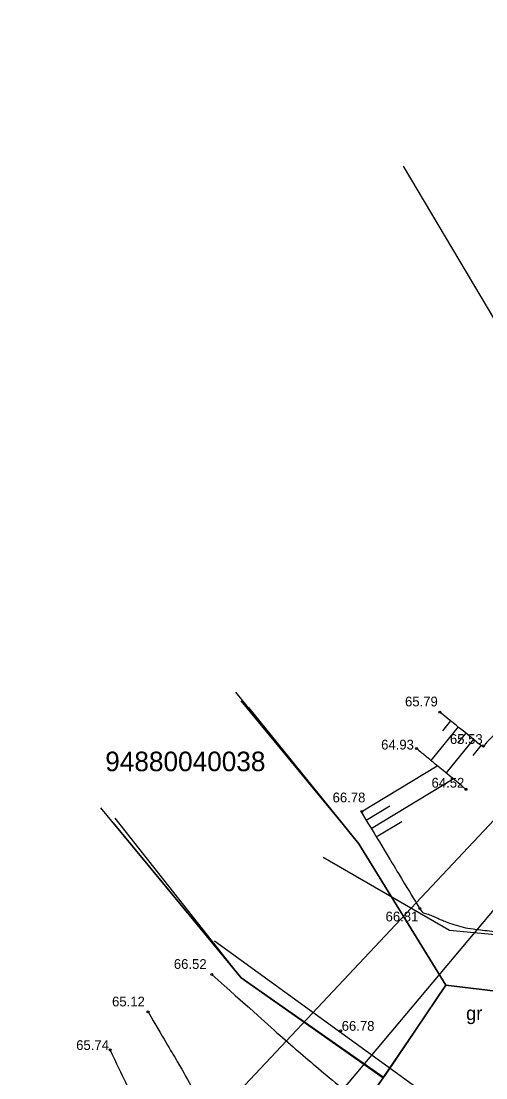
# Model space of a CAD drawing. Extents: x 616607 to 617499, y 408385 to 409695.
# Drawn here: x 617313.7 to 617337.4, y 409529.6 to 409583.6 of the extents above; entities that cross this region are included whole.
import ezdxf

# ---------------------------------------------------------------- set-up
doc = ezdxf.new("R2010")
doc.units = 0
for name, color, linetype in [('BUVE_INZE_VEKT_####_#', 7, 'Continuous'), ('CELI_CMAL_####_####_#', 7, 'Continuous'), ('CELI_CSEG_####_TKST_#', 7, 'Continuous'), ('DREN_VADP_####_####_#', 7, 'Continuous'), ('HIDT_CAUR_####_####_#', 7, 'Continuous'), ('RAMI_UZMR_####_####_#', 7, 'Continuous'), ('RELJ_AATZ_####_TKST_#', 7, 'Continuous'), ('RELJ_ELEM_####_####_#', 7, 'Continuous'), ('RELJ_NOGA_####_####_#', 7, 'Continuous'), ('RELJ_NOGL_####_####_#', 7, 'Continuous'), ('ROBZ_IERR_####_####_#', 7, 'Continuous'), ('ROBZ_PROJ_####_####_#', 7, 'Continuous'), ('ROBZ_PROJ_####_TKST_#', 7, 'Continuous'), ('ROBZ_UZMR_####_####_#', 7, 'Continuous')]:
    doc.layers.add(name, color=color, linetype=linetype)

# ---------------------------------------------------------------- blocks, each defined once
blk = doc.blocks.new('PKT')
at = {"layer": 'RELJ_ELEM_####_####_#'}
blk.add_circle((0, 0), 0.05, dxfattribs=at)

msp = doc.modelspace()

# ---------------------------------------------------------------- linework, layer by layer
at = {"layer": 'BUVE_INZE_VEKT_####_#'}
msp.add_lwpolyline([(617324.923, 409548.853), (617330.95, 409541.554), (617335.391, 409534.333), (617332.184, 409529.625), (617324.935, 409534.695), (617318.501, 409542.857)], dxfattribs=at)
at = {"layer": 'CELI_CMAL_####_####_#'}
for points in [[(617329.129, 409540.872), (617335.578, 409537.138), (617339.527, 409536.758), (617344.023, 409537.049), (617347.209, 409538.054), (617350.956, 409540.638)], [(617323.58, 409536.589), (617338.621, 409525.673)]]:
    msp.add_lwpolyline(points, dxfattribs=at)
at = {"layer": 'DREN_VADP_####_####_#'}
msp.add_lwpolyline([(617345.447, 409555.599), (617333.219, 409576.192)], dxfattribs=at)
at = {"layer": 'HIDT_CAUR_####_####_#'}
msp.add_lwpolyline([(617328.298, 409526.812), (617339.023, 409539.598)], dxfattribs=at)
at = {"layer": 'RAMI_UZMR_####_####_#'}
msp.add_lwpolyline([(617101.571, 408748.246), (617213.472, 409074.039), (617215.883, 409140.56), (617165.121, 409241.478), (617252.137, 409353.424), (617269.572, 409425.099), (617332.631, 409510.312), (617439.945, 409622.037), (617425.373, 409635.959), (617242.079, 409440.82), (617216.614, 409355.716), (617136.613, 409246.751), (617191.828, 409115.62), (617145.545, 408952.8)], dxfattribs=at)
at = {"layer": 'RELJ_NOGA_####_####_#'}
for p, q in [((617335.629, 409547.841), (617335.211, 409547.327)), ((617335.241, 409548.156), (617335.241, 409548.155)), ((617335.629, 409547.841), (617335.629, 409547.84)), ((617336.017, 409547.525), (617334.623, 409545.811)), ((617336.405, 409547.209), (617335.986, 409546.695)), ((617336.017, 409547.525), (617336.016, 409547.524)), ((617336.405, 409547.209), (617336.405, 409547.209)), ((617336.793, 409546.894), (617335.395, 409545.176)), ((617336.793, 409546.894), (617336.792, 409546.893)), ((617337.18, 409546.578), (617336.761, 409546.062)), ((617337.18, 409546.578), (617337.18, 409546.578)), ((617331.056, 409543.191), (617334.945, 409545.545)), ((617331.574, 409542.336), (617335.764, 409544.872)), ((617331.315, 409542.764), (617332.527, 409543.497)), ((617331.056, 409543.191), (617331.057, 409543.192)), ((617331.315, 409542.764), (617331.315, 409542.764)), ((617331.574, 409542.336), (617331.575, 409542.336)), ((617331.833, 409541.908), (617333.135, 409542.696)), ((617331.833, 409541.908), (617331.833, 409541.908)), ((617332.092, 409541.48), (617332.092, 409541.481)), ((617332.35, 409541.053), (617332.351, 409541.053)), ((617332.609, 409540.625), (617332.61, 409540.625)), ((617332.868, 409540.197), (617332.868, 409540.197)), ((617333.127, 409539.769), (617333.128, 409539.77)), ((617333.386, 409539.342), (617333.386, 409539.342)), ((617333.645, 409538.914), (617333.646, 409538.914)), ((617333.904, 409538.486), (617333.904, 409538.486)), ((617334.2, 409538.089), (617334.201, 409538.09)), ((617334.656, 409537.887), (617334.656, 409537.888)), ((617335.113, 409537.684), (617335.113, 409537.685)), ((617335.58, 409537.506), (617335.58, 409537.506)), ((617335.58, 409537.506), (617335.58, 409537.506)), ((617336.057, 409537.357), (617336.057, 409537.358)), ((617336.057, 409537.356), (617336.057, 409537.357)), ((617336.543, 409537.24), (617336.543, 409537.24)), ((617336.544, 409537.242), (617336.544, 409537.242)), ((617337.038, 409537.168), (617337.038, 409537.169)), ((617337.038, 409537.167), (617337.038, 409537.168)), ((617318.26, 409530.987), (617318.259, 409530.987)), ((617318.26, 409530.987), (617318.261, 409530.988)), ((617318.477, 409530.537), (617318.476, 409530.537)), ((617318.477, 409530.537), (617318.477, 409530.537)), ((617318.694, 409530.086), (617318.693, 409530.086)), ((617318.694, 409530.086), (617318.694, 409530.087)), ((617318.911, 409529.636), (617318.91, 409529.636)), ((617318.911, 409529.636), (617318.911, 409529.636))]:
    msp.add_line(p, q, dxfattribs=at)
for points in [[(617405.903, 409615.582), (617390.969, 409600.632), (617376.035, 409585.682), (617361.1, 409570.732), (617353.162, 409562.786), (617345.334, 409554.728), (617337.455, 409546.726), (617337.388, 409546.658), (617337.328, 409546.458), (617337.253, 409546.519), (617336.529, 409547.109), (617335.804, 409547.698), (617335.079, 409548.288)], [(617331.056, 409543.191), (617332.054, 409541.542), (617333.052, 409539.893), (617334.051, 409538.243), (617334.188, 409538.016), (617334.501, 409537.961), (617334.744, 409537.85), (617334.977, 409537.743), (617335.205, 409537.638), (617335.447, 409537.552), (617335.916, 409537.385), (617336.387, 409537.247), (617336.878, 409537.187), (617337.849, 409537.069), (617338.82, 409537.003), (617339.794, 409537), (617340.122, 409536.999), (617340.45, 409536.997), (617340.777, 409537.001)], [(617323.43, 409534.875), (617325.254, 409533.269), (617327.041, 409531.618), (617328.903, 409530.056), (617331.485, 409527.887), (617334.171, 409525.842), (617336.806, 409523.735)], [(617148.095, 409250.281), (617149.367, 409254.282), (617150.639, 409258.284), (617151.912, 409262.285), (617156.597, 409277.022), (617171.021, 409286.603), (617180.379, 409298.915), (617194.802, 409317.89), (617212.921, 409334.355), (617223.034, 409356.295), (617225.913, 409362.541), (617226.817, 409369.327), (617228.782, 409375.821), (617233.86, 409392.605), (617237.843, 409409.628), (617244.376, 409426.063), (617252.258, 409445.895), (617268.673, 409460.708), (617281.86, 409477.296), (617294.583, 409493.301), (617307.725, 409508.821), (617320.496, 409524.825), (617320.543, 409524.885), (617320.584, 409524.948), (617320.623, 409525.013), (617320.843, 409525.374), (617320.906, 409525.909), (617320.728, 409526.275), (617320.636, 409526.463), (617320.388, 409526.567), (617320.294, 409526.764), (617319.61, 409528.184), (617318.926, 409529.604), (617318.242, 409531.024)]]:
    msp.add_open_spline(points, degree=3, dxfattribs=at)
at = {"layer": 'RELJ_NOGL_####_####_#'}
for points in [[(617336.415, 409544.336), (617335.809, 409544.835), (617335.203, 409545.333), (617334.597, 409545.832), (617334.359, 409546.028), (617334.122, 409546.224), (617333.884, 409546.421)], [(617320.178, 409532.963), (617320.946, 409531.637), (617321.747, 409530.328), (617322.481, 409528.983), (617323.001, 409528.03), (617323.474, 409527.05), (617323.97, 409526.084)]]:
    msp.add_open_spline(points, degree=3, dxfattribs=at)
at = {"layer": 'ROBZ_IERR_####_####_#'}
msp.add_lwpolyline([(617350.237, 409580.038), (617370.73, 409556.7), (617349.913, 409536.856), (617341.051, 409533.641), (617335.391, 409534.333), (617330.95, 409541.554), (617324.668, 409549.301)], dxfattribs=at)
at = {"layer": 'ROBZ_PROJ_####_####_#'}
for points in [[(617325.305, 409548.516), (617330.95, 409541.554), (617335.391, 409534.333), (617332.358, 409529.835), (617332.188, 409529.592), (617324.935, 409534.695), (617317.766, 409543.393)], [(617318.399, 409542.625), (617324.935, 409534.695), (617332.188, 409529.592), (617326.39, 409521.291), (617255.789, 409432.426), (617250.98, 409414.497), (617224.174, 409428.057)]]:
    msp.add_lwpolyline(points, dxfattribs=at)
at = {"layer": 'ROBZ_UZMR_####_####_#'}
msp.add_lwpolyline([(617232.583, 409073.745), (617196.025, 409075.262), (617200.886, 409119.423), (617196.507, 409136.07), (617150.138, 409230.13), (617148.652, 409247.272), (617201.229, 409318.934), (617233.453, 409357.938), (617244.928, 409391.934), (617250.98, 409414.497), (617255.789, 409432.426), (617326.39, 409521.291), (617332.188, 409529.592), (617332.358, 409529.835), (617335.391, 409534.333), (617341.051, 409533.641), (617349.913, 409536.856), (617370.73, 409556.7), (617378.749, 409547.935), (617381.343, 409545.1)], dxfattribs=at)

# ---------------------------------------------------------------- block references
at = {"layer": 'RELJ_ELEM_####_####_#'}
for p in [(617335.079, 409548.288), (617333.884, 409546.421), (617337.289, 409546.555), (617336.415, 409544.336), (617331.103, 409543.209), (617334.051, 409538.243), (617323.43, 409534.875), (617320.178, 409532.963), (617330.015, 409531.99), (617318.242, 409531.024)]:
    msp.add_blockref('PKT', p, dxfattribs=at)

# ---------------------------------------------------------------- texts
at = {"layer": 'CELI_CSEG_####_TKST_#'}
msp.add_text('gr', height=0.7, dxfattribs=at).set_placement((617336.418, 409532.541))
at = {"layer": 'RELJ_AATZ_####_TKST_#'}
for s, p in [('65.79', (617333.302, 409548.576)), ('64.93', (617332.082, 409546.371)), ('65.53', (617335.594, 409546.658)), ('64.52', (617334.655, 409544.423)), ('66.78', (617329.605, 409543.67)), ('66.81', (617332.308, 409537.586)), ('66.52', (617321.498, 409535.158)), ('65.12', (617318.342, 409533.24)), ('66.78', (617330.068, 409531.995)), ('65.74', (617316.51, 409531.012))]:
    msp.add_text(s, height=0.5, dxfattribs=at).set_placement(p)
at = {"layer": 'ROBZ_PROJ_####_TKST_#'}
msp.add_text('94880040038', height=1, dxfattribs=at).set_placement((617317.994, 409545.264))

doc.saveas('drawing.dxf')
